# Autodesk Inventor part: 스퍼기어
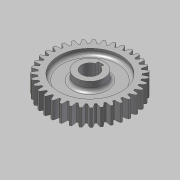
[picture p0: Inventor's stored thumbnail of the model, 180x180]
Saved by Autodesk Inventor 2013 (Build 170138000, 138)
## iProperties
Created: 2013-08
Part Number: 스퍼기어
Material: 강
Document SubType Name: Modeling
Designer: 한국산업디자인학원
Categories: <?xml version="1.0" encoding="UTF-16"?> <MemberInstance><Categories><FamilyTemplate><FamilyTemplateParameter ValueType="xs:double" Id="1" ObjectReferenceKey="da
Density: 1 g/cm^3
CustomPartVersion: 1
Author: 한국산업디자인학원
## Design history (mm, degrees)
sketch "Sketch1"
  geometry: C1 r 37 at (0, 0)
  constraints: 1 centre point
  dimensions: "d0" = 74 diameter of C1 (= da_da)
extrude "Extrusion1" new body sketch "Sketch1" distance "d1" = 15 (= da_b); taper "d2" = 0 deg
workplane "Work Plane2"
feature "피치 지름" dims "d4" = 10, "d5" = 0
workplane "Work Plane8"
workplane "Work Plane9"
feature "스퍼 기어" dims "da_b" = 15, "da_d" = 70, "da_aw" = 70, "da_da" = 74, "da_df" = 65, "da_dw" = 70, angle "da_beta" = 0 deg, "da_lefttooth" = 0, "da_righttooth" = 0
node "작업 평면11"
sketch "스케치3"
  geometry: C1 r 12.5 at (0, 0); 1 further point
  constraints: 1 centre point, 1 coincident
  dimensions: "d50" = 25 diameter of C1
extrude "돌출2" join sketch "스케치3" distance "d51" = 31; taper "d52" = 0 deg
hole "구멍1" diameter "d55" = 15; stored, may be unused: countersink angle "d59" = 90 deg, drill point angle "d61" = 118 deg; dims "d53" = 10, "d54" = 10, "d56" = 6, "d57" = 4, "d58" = 2, "d60" = 8
sketch "스케치4"
  geometry: C1 r 12.5 at (0, 0) reference; C2 r 27.5 at (0, 0); C3 r 12.5 at (0, 0); A1 r 37 centre (0, 0) between (-5.788, 36.544) and (-7.422, 36.248) reference
  constraints: 2 centre point, 2 coincident, 1 concentric
  dimensions: "d62" = 55 diameter of C2
extrude "돌출3" cut sketch "스케치4" distance "d63" = 5; taper "d64" = 0 deg
node "작업 평면12"
fillet "모깎기1" dims "d65" = 3
sketch "스케치5"
  geometry: L1 (-2.5, 9.8)-(2.5, 9.8); L2 (0, 9.8)-(0, -7.5); L3 (-2.5, 9.8)-(-2.5, 7.071); L4 (2.5, 9.8)-(2.5, 7.071); L5 (-2.5, 7.071)-(2.5, 7.071); A1 r 7.5 centre (0, 0) between (0, -7.5) and (-2.5, 7.071) reference
  constraints: 10 end point, 4 point on circle, 2 parallel, 2 perpendicular, 1 horizontal, 1 midpoint, 1 vertical alignment
  dimensions: "d66" = 5 distance of L1.start L1.end; "d68" = 17.3 distance of L2.start L2.end
extrude "돌출4" cut sketch "스케치5" stored distance "d69" = 5; taper "d70" = 0 deg
body "Solid1"
mirror "대칭1"
sketch "Sketch2"
  geometry: C1 r 37 at (0, 0) reference; C2 r 35 at (0, 0)
  constraints: 1 centre point, 1 coincident
  dimensions: "d3" = 70 diameter of C2 (= da_dw)
body "Srf1"
other parameters: "d17" = 0, "d34" = 0.8976 (computed from da_z), "d39" = 0, "d41" = 0, "d47" = 0, "d48" = 0, "d49" = 3
